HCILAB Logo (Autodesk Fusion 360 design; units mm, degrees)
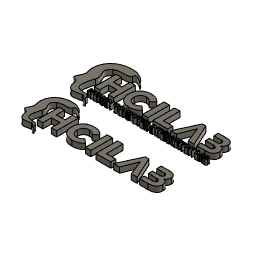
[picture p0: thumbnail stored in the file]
extrude "Extrude1" new body blind 5
extrude "Extrude2" cut of existing geometry blind -2
move "Move1"
extrude "Extrude3" add of existing geometry blind 1
extrude "Extrude4" cut of existing geometry blind -1
extrude "Extrude5" cut of existing geometry blind -1
move "Move2"
extrude "Extrude6" new body blind 5 bodies "T (1)", "R (1)"
extrude "Extrude7" add of existing geometry blind 0.3
extrude "Extrude8" cut of existing geometry blind -0.3
extrude "Extrude9" cut of existing geometry blind -0.4
move "Move3"
move "Move4"
move "Move5"
move "Move6"
move "Move7"
move "Move8"
move "Move9"
scale "Scale1" ScaleFactor 1.0172
move "Move10"
move "Move11"
move "Move12"
move "Move13"
move "Move14"
move "Move15"
extrude "Extrude10" add blind -5.086
extrude "Extrude11" cut of existing geometry blind -0.0001 (= "-5.000E-05 mm")
extrude "Extrude12" cut of existing geometry blind -0.0001 (= "-5.000E-05 mm")
extrude "Extrude13" add blind -5.086
extrude "Extrude14" cut of existing geometry blind -0.0001 (= "-5.000E-05 mm")
extrude "Extrude15" add blind -5.086
extrude "Extrude16" cut of existing geometry blind -0.0001 (= "-5.000E-05 mm")
extrude "Extrude17" add blind -5.086
extrude "Extrude18" cut of existing geometry blind -0.0001 (= "-5.000E-05 mm")
extrude "Extrude19" new body blind 5 bodies "HEAD"
extrude "Extrude20" cut of existing geometry blind -0.086
copy_paste_bodies "CopyPasteBodies2"
move "Move19"
remove_body "RemoveBody1"
remove_body "RemoveBody2"
remove_body "RemoveBody3"
remove_body "RemoveBody4"
remove_body "RemoveBody5"
remove_body "RemoveBody6"
remove_body "RemoveBody7"
remove_body "RemoveBody8"
remove_body "RemoveBody9"
remove_body "RemoveBody10"
remove_body "RemoveBody11"
remove_body "RemoveBody12"
remove_body "RemoveBody13"
remove_body "RemoveBody14"
remove_body "RemoveBody15"
remove_body "RemoveBody16"
remove_body "RemoveBody17"
remove_body "RemoveBody18"
remove_body "RemoveBody19"
remove_body "RemoveBody20"
remove_body "RemoveBody21"
remove_body "RemoveBody22"
remove_body "RemoveBody23"
remove_body "RemoveBody24"
remove_body "RemoveBody25"
remove_body "RemoveBody26"
remove_body "RemoveBody27"
move "Move20"
scale "Scale3" ScaleFactor 0.8194
move "Move21"
extrude "Extrude21" add of existing geometry blind 0.903
sketch "V2" plane through (0, 5.0002, 0) normal (0, 1, 0) x axis (-1, 0, 0)
  curve K1 (12.7693, 61.984) -> (13.6443, 57.0254)
  curve K2 (14.9569, 69.4219) -> (12.7693, 61.984)
  curve K3 (12.3316, 71.0263) -> (14.9569, 69.4219)
  curve K4 (11.0918, 73.141) -> (12.3316, 71.0263)
  curve K5 (7.6645, 79.0476) -> (11.0918, 73.141)
  curve K6 (0.0807, 78.2454) -> (7.6645, 79.0476)
  curve K7 (-4.7506, 80.717) -> (0.0807, 78.2454)
  curve K8 (-3.389, 79.5703) -> (-4.7506, 80.717)
  curve K9 (-2.2528, 76.86) -> (-3.389, 79.5703)
  curve K10 (5.4769, 75.183) -> (-2.2528, 76.86)
  curve K11 (5.331, 63.0052) -> (5.4769, 75.183)
  curve K12 (4.8206, 50.3898) -> (5.331, 63.0052)
  curve K13 (-7.0656, 47.4) -> (4.8206, 50.3898)
  curve K14 (-14.4307, 49.077) -> (-7.0656, 47.4)
  curve K15 (-2.508, 42.8786) -> (-14.4307, 49.077)
  curve K16 (13.6443, 57.0254) -> (-2.508, 42.8786)
  line L1 (-94.1408, 60.9984) -> (-101.0176, 60.9984)
  curve K17 (-108.127, 57.6541) -> (-105.5182, 62.0038)
  curve K18 (-104.5657, 66.6922) -> (-101.7055, 64.6999)
  curve K19 (-103.4306, 58.9796) -> (-101.1446, 56.9979)
  curve K20 (-101.0176, 60.9984) -> (-103.4306, 58.9796)
  line L2 (-12.8535, 60.39) -> (-12.8535, 52.8916)
  curve K21 (-101.8722, 68.6687) -> (-104.5657, 66.6922)
  line L3 (-94.1408, 52.8916) -> (-101.4806, 52.8916)
  line L4 (-101.1446, 56.9979) -> (-94.1408, 56.9979)
  curve K22 (-101.4806, 52.8916) -> (-108.127, 57.6541)
  line L5 (-12.8535, 52.8916) -> (-17.7615, 52.8916)
  line L6 (-94.1408, 56.9979) -> (-94.1408, 52.8916)
  line L7 (-67.6431, 68.2374) -> (-67.6431, 72.8332)
  line L8 (-75.6068, 72.8332) -> (-70.2226, 72.8332)
  line L9 (-49.2996, 72.8332) -> (-44.2725, 72.8332)
  curve K23 (-32.1468, 73.2539) -> (-21.537, 62.8188)
  line L10 (-5.0006, 72.8332) -> (0, 72.8332)
  curve K24 (-21.537, 62.8188) -> (-32.1388, 52.5)
  curve K25 (-32.1388, 52.5) -> (-40.9521, 56.3418)
  line L11 (-67.6431, 72.8332) -> (-53.9111, 72.8332)
  curve K26 (-32.3055, 57.1276) -> (-26.6963, 62.8214)
  line L12 (-49.2996, 52.8916) -> (-49.2996, 72.8332)
  line L13 (-12.8535, 64.8773) -> (-5.0006, 64.8773)
  line L14 (-12.8535, 72.8332) -> (-12.8535, 64.8773)
  line L15 (-81.0758, 59.0352) -> (-75.6068, 72.8332)
  curve K27 (-109.6404, 66.888) -> (-101.8458, 72.8332)
  line L16 (-94.1408, 68.6687) -> (-101.8722, 68.6687)
  line L17 (-82.7162, 52.8651) -> (-91.8866, 72.8332)
  line L18 (-44.2725, 52.8916) -> (-49.2996, 52.8916)
  line L19 (-58.9382, 52.8916) -> (-58.9382, 68.2374)
  line L20 (-101.7055, 64.6999) -> (-94.1408, 64.6999)
  line L21 (-79.4063, 52.8651) -> (-82.7162, 52.8651)
  line L22 (-44.2725, 72.8332) -> (-44.2725, 52.8916)
  line L23 (-5.0006, 52.8916) -> (-5.0006, 60.39)
  line L24 (-101.8458, 72.8332) -> (-94.1408, 72.8332)
  curve K28 (-105.5182, 62.0038) -> (-109.6404, 66.888)
  line L25 (-94.1408, 72.8332) -> (-94.1408, 68.6687)
  line L26 (-53.9111, 72.8332) -> (-53.9111, 52.8916)
  line L27 (-17.7615, 72.8332) -> (-12.8535, 72.8332)
  line L28 (-86.4891, 72.8332) -> (-81.0758, 59.0352)
  line L29 (-5.0006, 60.39) -> (-12.8535, 60.39)
  line L30 (-91.8866, 72.8332) -> (-86.4891, 72.8332)
  line L31 (-0.09, 52.8916) -> (-5.0006, 52.8916)
  line L32 (-37.1024, 66.2583) -> (-40.9521, 69.4677)
  line L33 (-17.7615, 52.8916) -> (-17.7615, 72.8332)
  line L34 (-53.9111, 52.8916) -> (-58.9382, 52.8916)
  line L35 (0, 72.8332) -> (-0.09, 52.8916)
  line L36 (-5.0006, 64.8773) -> (-5.0006, 72.8332)
  line L37 (-94.1408, 64.6999) -> (-94.1408, 60.9984)
  line L38 (-70.2226, 72.8332) -> (-79.4063, 52.8651)
  curve K29 (-26.6963, 62.8214) -> (-32.3055, 68.6396)
  curve K30 (-32.3055, 68.6396) -> (-37.1024, 66.2583)
  line L39 (-58.9382, 68.2374) -> (-67.6431, 68.2374)
  line L40 (-40.9521, 56.3418) -> (-37.1024, 59.5406)
  curve K31 (-40.9521, 69.4677) -> (-32.1468, 73.2539)
  arc A1 centre (-32.4408, 62.833) radius 5.7071 clockwise from (-32.3055, 57.1276) to (-37.1024, 59.5406)
sketch "V1" plane through (0, 5, 0) normal (0, 1, 0) x axis (-1, 0, 0)
  curve K1 (14.8095, 12.3608) -> (15.8773, 6.3096)
  curve K2 (17.4791, 21.4376) -> (14.8095, 12.3608)
  curve K3 (14.2753, 23.3955) -> (17.4791, 21.4376)
  curve K4 (12.7623, 25.9761) -> (14.2753, 23.3955)
  curve K5 (8.5799, 33.1842) -> (12.7623, 25.9761)
  curve K6 (-0.6749, 32.2053) -> (8.5799, 33.1842)
  curve K7 (-6.5707, 35.2214) -> (-0.6749, 32.2053)
  curve K8 (-4.9091, 33.8221) -> (-6.5707, 35.2214)
  curve K9 (-3.5226, 30.5146) -> (-4.9091, 33.8221)
  curve K10 (5.9103, 28.4681) -> (-3.5226, 30.5146)
  curve K11 (5.7322, 13.607) -> (5.9103, 28.4681)
  curve K12 (5.1094, -1.788) -> (5.7322, 13.607)
  curve K13 (-9.3958, -5.4365) -> (5.1094, -1.788)
  curve K14 (-18.3837, -3.3901) -> (-9.3958, -5.4365)
  curve K15 (-3.834, -10.9542) -> (-18.3837, -3.3901)
  curve K16 (15.8773, 6.3096) -> (-3.834, -10.9542)
  curve K17 (-32.1388, 0) -> (-40.9521, 3.8418)
  line L1 (-49.2996, 20.3332) -> (-44.2725, 20.3332)
  curve K18 (-26.6963, 10.3214) -> (-32.3055, 16.1396)
  line L2 (-49.2996, 0.3916) -> (-49.2996, 20.3332)
  line L3 (0, 20.3332) -> (-0.09, 0.3916)
  line L4 (-58.9382, 15.7374) -> (-67.6431, 15.7374)
  line L5 (-79.4063, 0.3651) -> (-82.7162, 0.3651)
  line L6 (-58.9382, 0.3916) -> (-58.9382, 15.7374)
  line L7 (-70.2226, 20.3332) -> (-79.4063, 0.3651)
  line L8 (-67.6431, 15.7374) -> (-67.6431, 20.3332)
  line L9 (-53.9111, 0.3916) -> (-58.9382, 0.3916)
  line L10 (-94.1408, 12.1999) -> (-94.1408, 8.4984)
  line L11 (-82.7162, 0.3651) -> (-91.8866, 20.3332)
  curve K19 (-21.537, 10.3187) -> (-32.1388, 0)
  curve K20 (-32.1468, 20.7539) -> (-21.537, 10.3187)
  line L12 (-5.0006, 12.3773) -> (-5.0006, 20.3332)
  line L13 (-53.9111, 20.3332) -> (-53.9111, 0.3916)
  line L14 (-75.6068, 20.3332) -> (-70.2226, 20.3332)
  line L15 (-5.0006, 20.3332) -> (0, 20.3332)
  curve K21 (-40.9521, 16.9677) -> (-32.1468, 20.7539)
  line L16 (-12.8535, 12.3773) -> (-5.0006, 12.3773)
  line L17 (-91.8866, 20.3332) -> (-86.4891, 20.3332)
  line L18 (-101.7055, 12.1999) -> (-94.1408, 12.1999)
  line L19 (-44.2725, 20.3332) -> (-44.2725, 0.3916)
  line L20 (-12.8535, 0.3916) -> (-17.7615, 0.3916)
  curve K22 (-101.8722, 16.1687) -> (-104.5657, 14.1922)
  line L21 (-44.2725, 0.3916) -> (-49.2996, 0.3916)
  curve K23 (-32.3055, 4.6276) -> (-26.6963, 10.3214)
  line L22 (-17.7615, 0.3916) -> (-17.7615, 20.3332)
  line L23 (-81.0758, 6.5352) -> (-75.6068, 20.3332)
  line L24 (-12.8535, 20.3332) -> (-12.8535, 12.3773)
  line L25 (-17.7615, 20.3332) -> (-12.8535, 20.3332)
  line L26 (-0.09, 0.3916) -> (-5.0006, 0.3916)
  line L27 (-40.9521, 3.8418) -> (-37.1024, 7.0406)
  line L28 (-94.1408, 16.1687) -> (-101.8722, 16.1687)
  line L29 (-37.1024, 13.7583) -> (-40.9521, 16.9677)
  line L30 (-94.1408, 0.3916) -> (-101.4806, 0.3916)
  curve K24 (-109.6404, 14.388) -> (-101.8458, 20.3332)
  line L31 (-94.1408, 20.3332) -> (-94.1408, 16.1687)
  line L32 (-12.8535, 7.89) -> (-12.8535, 0.3916)
  line L33 (-101.8458, 20.3332) -> (-94.1408, 20.3332)
  line L34 (-94.1408, 4.4979) -> (-94.1408, 0.3916)
  line L35 (-5.0006, 0.3916) -> (-5.0006, 7.89)
  line L36 (-101.1446, 4.4979) -> (-94.1408, 4.4979)
  curve K25 (-104.5657, 14.1922) -> (-101.7055, 12.1999)
  line L37 (-5.0006, 7.89) -> (-12.8535, 7.89)
  line L38 (-94.1408, 8.4984) -> (-101.0176, 8.4984)
  curve K26 (-101.0176, 8.4984) -> (-103.4306, 6.4796)
  curve K27 (-108.127, 5.1541) -> (-105.5182, 9.5038)
  curve K28 (-101.4806, 0.3916) -> (-108.127, 5.1541)
  curve K29 (-103.4306, 6.4796) -> (-101.1446, 4.4979)
  curve K30 (-105.5182, 9.5038) -> (-109.6404, 14.388)
  curve K31 (-32.3055, 16.1396) -> (-37.1024, 13.7583)
  line L39 (-86.4891, 20.3332) -> (-81.0758, 6.5352)
  line L40 (-67.6431, 20.3332) -> (-53.9111, 20.3332)
  line L41 (-10.3543, 24.9831) -> (-11.9448, 22.9485)
  line L42 (-14.9429, 24.1677) -> (-14.3765, 25.6006)
  line L43 (-15.4953, 25.6006) -> (-14.9429, 24.1677)
  line L44 (-48.3524, 26.9209) -> (-48.3524, 22.9674)
  line L45 (-8.761, 22.9485) -> (-10.3543, 24.9831)
  line L46 (-14.3765, 25.6006) -> (-15.4953, 25.6006)
  line L47 (-45.7176, 26.9182) -> (-45.7176, 23.8663)
  line L48 (-35.7812, 22.9485) -> (-36.2737, 22.9485)
  line L49 (-61.7491, 22.9674) -> (-62.718, 22.9674)
  curve K32 (-42.348, 27.0016) -> (-44.1055, 25.3626)
  line L50 (-66.9918, 22.9674) -> (-69.9738, 22.9674)
  line L51 (-86.1594, 26.9182) -> (-86.1594, 22.9674)
  line L52 (-51.4178, 26.0597) -> (-51.4178, 26.9209)
  line L53 (-17.4351, 26.9182) -> (-17.4351, 22.9485)
  line L54 (0.0208, 26.9048) -> (0.0208, 22.9674)
  line L55 (-4.1131, 22.9674) -> (-5.1089, 22.9674)
  line L56 (-83.468, 23.8663) -> (-82.257, 23.8663)
  curve K33 (-87.7526, 24.932) -> (-89.8922, 26.9882)
  line L57 (-4.1131, 25.3492) -> (-4.1131, 22.9674)
  line L58 (-20.113, 25.1339) -> (-20.113, 22.9674)
  line L59 (-49.3078, 26.0597) -> (-51.4178, 26.0597)
  line L60 (-82.257, 22.9674) -> (-85.6534, 22.9674)
  curve K34 (-4.1131, 25.3492) -> (-5.8651, 27.0016)
  line L61 (-5.1089, 22.9674) -> (-5.1089, 25.1204)
  line L62 (-18.4013, 26.9182) -> (-17.4351, 26.9182)
  line L63 (-49.3078, 25.3815) -> (-49.3078, 26.0597)
  line L64 (-17.4351, 22.9485) -> (-17.9303, 22.9485)
  line L65 (-51.0248, 25.3815) -> (-49.3078, 25.3815)
  curve K35 (-5.8651, 27.0016) -> (-7.6199, 25.3626)
  line L66 (-17.9303, 22.9485) -> (-20.113, 25.1339)
  line L67 (-83.468, 26.9182) -> (-83.468, 23.8663)
  line L68 (-66.9918, 26.9209) -> (-66.9918, 22.9674)
  line L69 (-49.3078, 24.5741) -> (-51.0248, 24.5741)
  curve K36 (-89.8922, 22.8705) -> (-87.7526, 24.932)
  line L70 (-51.0248, 24.5741) -> (-51.0248, 25.3815)
  line L71 (-85.6534, 22.9674) -> (-85.6534, 23.8797)
  line L72 (-49.3078, 23.8286) -> (-49.3078, 24.5741)
  line L73 (-98.7018, 26.9182) -> (-98.7018, 22.9674)
  line L74 (-69.9738, 22.9674) -> (-69.9738, 23.8286)
  line L75 (-0.9508, 26.9048) -> (0.0208, 26.9048)
  curve K37 (-43.1151, 25.1204) -> (-42.348, 26.0758)
  line L76 (-85.6534, 23.8797) -> (-84.4638, 23.8797)
  curve K38 (-39.21, 24.4557) -> (-38.4645, 25.1043)
  line L77 (-99.6976, 26.0085) -> (-101.6192, 26.0085)
  line L78 (-87.1525, 22.9674) -> (-87.1525, 26.9182)
  line L79 (-67.9365, 24.5741) -> (-69.6535, 24.5741)
  curve K39 (-38.486, 23.799) -> (-39.21, 24.4557)
  line L80 (-86.1594, 22.9674) -> (-87.1525, 22.9674)
  curve K40 (-6.6322, 25.1204) -> (-5.8651, 26.0758)
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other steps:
base_feature "Base Feature" bodies "HEAD"
named bodies: "T (1)", "R (1)", "E (1)", "I (1)", "C (1)", "O (1)", "T (2)", "N (1)", "A (1)", "HEAD", "HEAD (1)", "R (1) (1)", "P (1)", "E (1) (1)", "U (1)", "C (1) (1)", "O (1) (1)", "T (2) (1)", "M (1)", "E (2)", "T (3)", "C (2)", "N (2)", "I (2)", "R (2)", "I (1) (1)", "N (1) (1)", "A (1) (1)", "O (2)", "T (1) (1)", "B (1)", "A (2)", "L (1)"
